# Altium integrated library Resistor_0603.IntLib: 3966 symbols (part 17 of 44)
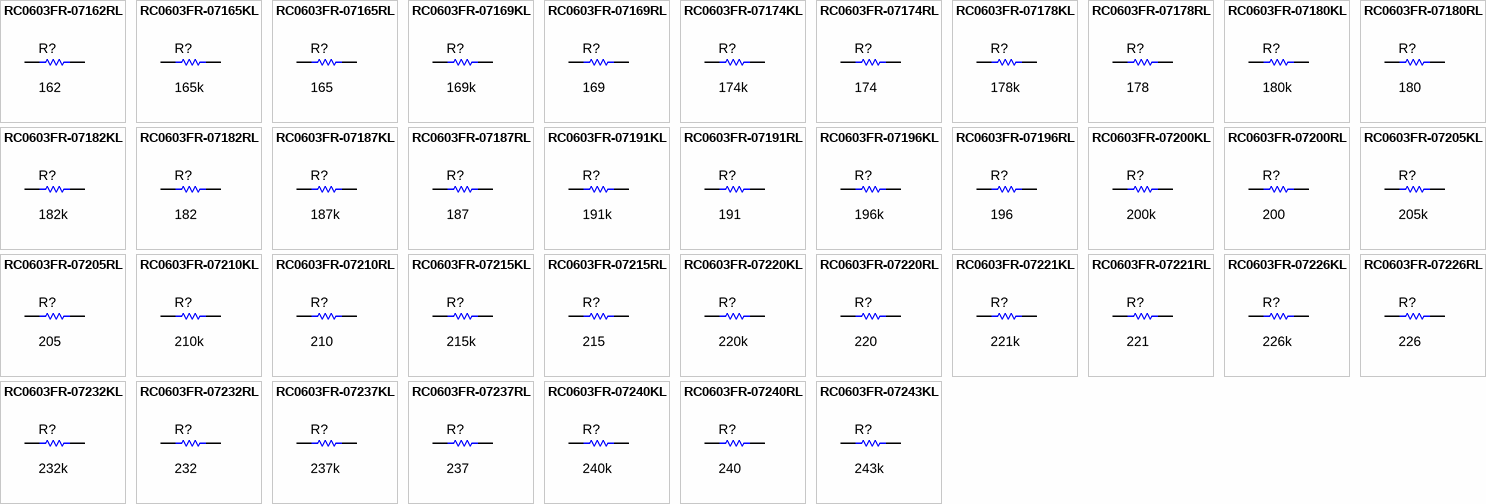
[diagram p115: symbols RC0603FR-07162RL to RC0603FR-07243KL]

## RC0603FR-07240RL
designator R?  ValueDisplayed: 240  (hidden comment: RC0603FR-07240RL)
RES, 240, 1%, 0.1 W, 0603; Manufacturer: Yageo America; CompType: Resistor; Value: 240; Value_Code: 240R; Tolerance_%: 1; Power_W: 0.1; Value2: 0.1W; VDC_V: 150; TempCo: 200 ppm/C; SizeArea_mm2: 1.28; SizeX_mm: 1.6; SizeY_mm: 0.8; U/M: EA; AEC Category: Q200; Green_Lifecycle: Active; Green_REACh: Passed
signal-integrity model Resistor
simulation model Resistor
footprint 0603
footprint 0603M
footprint 0603L
footprint 0603_HV
footprint 0603S
pins: 1, 2

## RC0603FR-07243KL
designator R?  ValueDisplayed: 243k  (hidden comment: RC0603FR-07243KL)
RES, 243 k, 1%, 0.1 W, 0603; Manufacturer: Yageo America; CompType: Resistor; Value: 243k; Res_ohm: 243000; Tolerance_%: 1; Power_W: 0.1; Value2: 0.1W; VDC_V: 150; TempCo: 200 ppm/C; SizeArea_mm2: 1.28; SizeX_mm: 1.6; SizeY_mm: 0.8; EIA_Code: E96; U/M: EA; AEC Category: Q200; Green_Lifecycle: Active; Green_REACh: Passed
signal-integrity model Resistor
simulation model Resistor
footprint 0603
footprint 0603M
footprint 0603L
footprint 0603_HV
footprint 0603S
pins: 1, 2

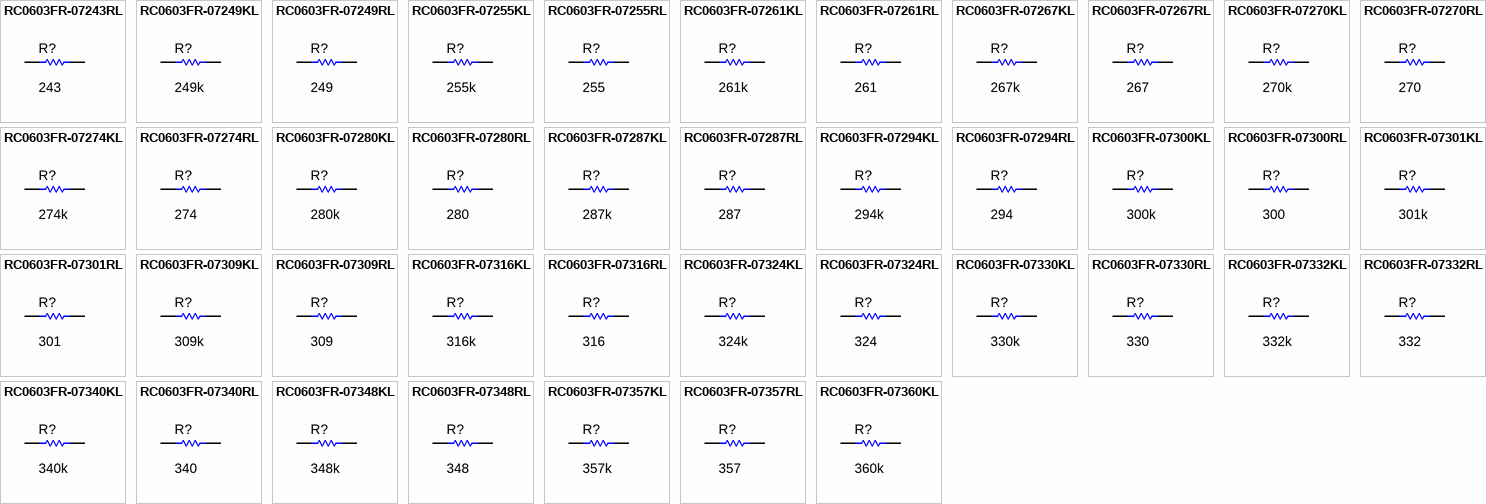
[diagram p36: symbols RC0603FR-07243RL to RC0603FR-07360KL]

## RC0603FR-07243RL
designator R?  ValueDisplayed: 243  (hidden comment: RC0603FR-07243RL)
RES, 243, 1%, 0.1 W, 0603; Manufacturer: Yageo America; CompType: Resistor; Value: 243; Value_Code: 243R; Tolerance_%: 1; Power_W: 0.1; Value2: 0.1W; VDC_V: 150; TempCo: 200 ppm/C; SizeArea_mm2: 1.28; SizeX_mm: 1.6; SizeY_mm: 0.8; EIA_Code: E96; U/M: EA; AEC Category: Q200
signal-integrity model Resistor
simulation model Resistor
footprint 0603
footprint 0603M
footprint 0603L
footprint 0603_HV
footprint 0603S
pins: 1, 2

## RC0603FR-07249KL
designator R?  ValueDisplayed: 249k  (hidden comment: RC0603FR-07249KL)
RES, 249 k, 1%, 0.1 W, 0603; Manufacturer: Yageo America; CompType: Resistor; Value: 249k; Res_ohm: 249000; Tolerance_%: 1; Power_W: 0.1; Value2: 0.1W; VDC_V: 150; TempCo: 200 ppm/C; SizeArea_mm2: 1.28; SizeX_mm: 1.6; SizeY_mm: 0.8; EIA_Code: E96; U/M: EA; AEC Category: Q200; Green_Lifecycle: Active; Green_REACh: Passed
signal-integrity model Resistor
simulation model Resistor
footprint 0603
footprint 0603M
footprint 0603L
footprint 0603_HV
footprint 0603S
pins: 1, 2

## RC0603FR-07249RL
designator R?  ValueDisplayed: 249  (hidden comment: RC0603FR-07249RL)
RES, 249, 1%, 0.1 W, 0603; Manufacturer: Yageo America; CompType: Resistor; Value: 249; Value_Code: 249R; Tolerance_%: 1; Power_W: 0.1; Value2: 0.1W; VDC_V: 150; TempCo: 200 ppm/C; SizeArea_mm2: 1.28; SizeX_mm: 1.6; SizeY_mm: 0.8; EIA_Code: E96; U/M: EA; AEC Category: Q200; Green_Lifecycle: Active; Green_REACh: Passed
signal-integrity model Resistor
simulation model Resistor
footprint 0603
footprint 0603M
footprint 0603L
footprint 0603_HV
footprint 0603S
pins: 1, 2

## RC0603FR-07255KL
designator R?  ValueDisplayed: 255k  (hidden comment: RC0603FR-07255KL)
RES, 255 k, 1%, 0.1 W, 0603; Manufacturer: Yageo America; CompType: Resistor; Value: 255k; Res_ohm: 255000; Tolerance_%: 1; Power_W: 0.1; Value2: 0.1W; VDC_V: 150; TempCo: 200 ppm/C; SizeArea_mm2: 1.28; SizeX_mm: 1.6; SizeY_mm: 0.8; EIA_Code: E96; U/M: EA; AEC Category: Q200; Green_Lifecycle: Active; Green_REACh: Passed
signal-integrity model Resistor
simulation model Resistor
footprint 0603
footprint 0603M
footprint 0603L
footprint 0603_HV
footprint 0603S
pins: 1, 2

## RC0603FR-07255RL
designator R?  ValueDisplayed: 255  (hidden comment: RC0603FR-07255RL)
RES, 255, 1%, 0.1 W, 0603; Manufacturer: Yageo America; CompType: Resistor; Value: 255; Value_Code: 255R; Tolerance_%: 1; Power_W: 0.1; Value2: 0.1W; VDC_V: 150; TempCo: 200 ppm/C; SizeArea_mm2: 1.28; SizeX_mm: 1.6; SizeY_mm: 0.8; EIA_Code: E96; U/M: EA; AEC Category: Q200
signal-integrity model Resistor
simulation model Resistor
footprint 0603
footprint 0603M
footprint 0603L
footprint 0603_HV
footprint 0603S
pins: 1, 2

## RC0603FR-07261KL
designator R?  ValueDisplayed: 261k  (hidden comment: RC0603FR-07261KL)
RES, 261 k, 1%, 0.1 W, 0603; Manufacturer: Yageo America; CompType: Resistor; Value: 261k; Res_ohm: 261000; Tolerance_%: 1; Power_W: 0.1; Value2: 0.1W; VDC_V: 150; TempCo: 200 ppm/C; SizeArea_mm2: 1.28; SizeX_mm: 1.6; SizeY_mm: 0.8; EIA_Code: E96; U/M: EA; AEC Category: Q200
signal-integrity model Resistor
simulation model Resistor
footprint 0603
footprint 0603M
footprint 0603L
footprint 0603_HV
footprint 0603S
pins: 1, 2

## RC0603FR-07261RL
designator R?  ValueDisplayed: 261  (hidden comment: RC0603FR-07261RL)
RES, 261, 1%, 0.1 W, 0603; Manufacturer: Yageo America; CompType: Resistor; Value: 261; Value_Code: 261R; Tolerance_%: 1; Power_W: 0.1; Value2: 0.1W; VDC_V: 150; TempCo: 200 ppm/C; SizeArea_mm2: 1.28; SizeX_mm: 1.6; SizeY_mm: 0.8; EIA_Code: E96; U/M: EA; AEC Category: Q200
signal-integrity model Resistor
simulation model Resistor
footprint 0603
footprint 0603M
footprint 0603L
footprint 0603_HV
footprint 0603S
pins: 1, 2

## RC0603FR-07267KL
designator R?  ValueDisplayed: 267k  (hidden comment: RC0603FR-07267KL)
RES, 267 k, 1%, 0.1 W, 0603; Manufacturer: Yageo America; CompType: Resistor; Value: 267k; Res_ohm: 267000; Tolerance_%: 1; Power_W: 0.1; Value2: 0.1W; VDC_V: 150; TempCo: 200 ppm/C; SizeArea_mm2: 1.28; SizeX_mm: 1.6; SizeY_mm: 0.8; EIA_Code: E96; U/M: EA; AEC Category: Q200
signal-integrity model Resistor
simulation model Resistor
footprint 0603
footprint 0603M
footprint 0603L
footprint 0603_HV
footprint 0603S
pins: 1, 2

## RC0603FR-07267RL
designator R?  ValueDisplayed: 267  (hidden comment: RC0603FR-07267RL)
RES, 267, 1%, 0.1 W, 0603; Manufacturer: Yageo America; CompType: Resistor; Value: 267; Value_Code: 267R; Tolerance_%: 1; Power_W: 0.1; Value2: 0.1W; VDC_V: 150; TempCo: 200 ppm/C; SizeArea_mm2: 1.28; SizeX_mm: 1.6; SizeY_mm: 0.8; EIA_Code: E96; U/M: EA; AEC Category: Q200
signal-integrity model Resistor
simulation model Resistor
footprint 0603
footprint 0603M
footprint 0603L
footprint 0603_HV
footprint 0603S
pins: 1, 2

## RC0603FR-07270KL
designator R?  ValueDisplayed: 270k  (hidden comment: RC0603FR-07270KL)
RES, 270 k, 1%, 0.1 W, 0603; Manufacturer: Yageo America; CompType: Resistor; Value: 270k; Res_ohm: 270000; Tolerance_%: 1; Power_W: 0.1; Value2: 0.1W; VDC_V: 150; TempCo: 200 ppm/C; SizeArea_mm2: 1.28; SizeX_mm: 1.6; SizeY_mm: 0.8; U/M: EA; AEC Category: Q200; Green_Lifecycle: Active; Green_REACh: Passed
signal-integrity model Resistor
simulation model Resistor
footprint 0603
footprint 0603M
footprint 0603L
footprint 0603_HV
footprint 0603S
pins: 1, 2

## RC0603FR-07270RL
designator R?  ValueDisplayed: 270  (hidden comment: RC0603FR-07270RL)
RES, 270, 1%, 0.1 W, 0603; Manufacturer: Yageo America; CompType: Resistor; Value: 270; Value_Code: 270R; Tolerance_%: 1; Power_W: 0.1; Value2: 0.1W; VDC_V: 150; TempCo: 200 ppm/C; SizeArea_mm2: 1.28; SizeX_mm: 1.6; SizeY_mm: 0.8; U/M: EA; AEC Category: Q200; Green_Lifecycle: Active; Green_REACh: Passed
signal-integrity model Resistor
simulation model Resistor
footprint 0603
footprint 0603M
footprint 0603L
footprint 0603_HV
footprint 0603S
pins: 1, 2

## RC0603FR-07274KL
designator R?  ValueDisplayed: 274k  (hidden comment: RC0603FR-07274KL)
RES, 274 k, 1%, 0.1 W, 0603; Manufacturer: Yageo America; CompType: Resistor; Value: 274k; Res_ohm: 274000; Tolerance_%: 1; Power_W: 0.1; Value2: 0.1W; VDC_V: 150; TempCo: 200 ppm/C; SizeArea_mm2: 1.28; SizeX_mm: 1.6; SizeY_mm: 0.8; EIA_Code: E96; U/M: EA; AEC Category: Q200; Green_Lifecycle: Active; Green_REACh: Passed
signal-integrity model Resistor
simulation model Resistor
footprint 0603
footprint 0603M
footprint 0603L
footprint 0603_HV
footprint 0603S
pins: 1, 2

## RC0603FR-07274RL
designator R?  ValueDisplayed: 274  (hidden comment: RC0603FR-07274RL)
RES, 274, 1%, 0.1 W, 0603; Manufacturer: Yageo America; CompType: Resistor; Value: 274; Value_Code: 274R; Tolerance_%: 1; Power_W: 0.1; Value2: 0.1W; VDC_V: 150; TempCo: 200 ppm/C; SizeArea_mm2: 1.28; SizeX_mm: 1.6; SizeY_mm: 0.8; EIA_Code: E96; U/M: EA; AEC Category: Q200
signal-integrity model Resistor
simulation model Resistor
footprint 0603
footprint 0603M
footprint 0603L
footprint 0603_HV
footprint 0603S
pins: 1, 2

## RC0603FR-07280KL
designator R?  ValueDisplayed: 280k  (hidden comment: RC0603FR-07280KL)
RES, 280 k, 1%, 0.1 W, 0603; Manufacturer: Yageo America; CompType: Resistor; Value: 280k; Res_ohm: 280000; Tolerance_%: 1; Power_W: 0.1; Value2: 0.1W; VDC_V: 150; TempCo: 200 ppm/C; SizeArea_mm2: 1.28; SizeX_mm: 1.6; SizeY_mm: 0.8; EIA_Code: E96; U/M: EA; AEC Category: Q200; Green_Lifecycle: Active; Green_REACh: Passed
signal-integrity model Resistor
simulation model Resistor
footprint 0603
footprint 0603M
footprint 0603L
footprint 0603_HV
footprint 0603S
pins: 1, 2

## RC0603FR-07280RL
designator R?  ValueDisplayed: 280  (hidden comment: RC0603FR-07280RL)
RES, 280, 1%, 0.1 W, 0603; Manufacturer: Yageo America; CompType: Resistor; Value: 280; Value_Code: 280R; Tolerance_%: 1; Power_W: 0.1; Value2: 0.1W; VDC_V: 150; TempCo: 200 ppm/C; SizeArea_mm2: 1.28; SizeX_mm: 1.6; SizeY_mm: 0.8; EIA_Code: E96; U/M: EA; AEC Category: Q200
signal-integrity model Resistor
simulation model Resistor
footprint 0603
footprint 0603M
footprint 0603L
footprint 0603_HV
footprint 0603S
pins: 1, 2

## RC0603FR-07287KL
designator R?  ValueDisplayed: 287k  (hidden comment: RC0603FR-07287KL)
RES, 287 k, 1%, 0.1 W, 0603; Manufacturer: Yageo America; CompType: Resistor; Value: 287k; Res_ohm: 287000; Tolerance_%: 1; Power_W: 0.1; Value2: 0.1W; VDC_V: 150; TempCo: 200 ppm/C; SizeArea_mm2: 1.28; SizeX_mm: 1.6; SizeY_mm: 0.8; EIA_Code: E96; U/M: EA; AEC Category: Q200
signal-integrity model Resistor
simulation model Resistor
footprint 0603
footprint 0603M
footprint 0603L
footprint 0603_HV
footprint 0603S
pins: 1, 2

## RC0603FR-07287RL
designator R?  ValueDisplayed: 287  (hidden comment: RC0603FR-07287RL)
RES, 287, 1%, 0.1 W, 0603; Manufacturer: Yageo America; CompType: Resistor; Value: 287; Value_Code: 287R; Tolerance_%: 1; Power_W: 0.1; Value2: 0.1W; VDC_V: 150; TempCo: 200 ppm/C; SizeArea_mm2: 1.28; SizeX_mm: 1.6; SizeY_mm: 0.8; EIA_Code: E96; U/M: EA; AEC Category: Q200
signal-integrity model Resistor
simulation model Resistor
footprint 0603
footprint 0603M
footprint 0603L
footprint 0603_HV
footprint 0603S
pins: 1, 2

## RC0603FR-07294KL
designator R?  ValueDisplayed: 294k  (hidden comment: RC0603FR-07294KL)
RES, 294 k, 1%, 0.1 W, 0603; Manufacturer: Yageo America; CompType: Resistor; Value: 294k; Res_ohm: 294000; Tolerance_%: 1; Power_W: 0.1; Value2: 0.1W; VDC_V: 150; TempCo: 200 ppm/C; SizeArea_mm2: 1.28; SizeX_mm: 1.6; SizeY_mm: 0.8; EIA_Code: E96; U/M: EA; AEC Category: Q200; Green_Lifecycle: Active; Green_REACh: Passed
signal-integrity model Resistor
simulation model Resistor
footprint 0603
footprint 0603M
footprint 0603L
footprint 0603_HV
footprint 0603S
pins: 1, 2

## RC0603FR-07294RL
designator R?  ValueDisplayed: 294  (hidden comment: RC0603FR-07294RL)
RES, 294, 1%, 0.1 W, 0603; Manufacturer: Yageo America; CompType: Resistor; Value: 294; Value_Code: 294R; Tolerance_%: 1; Power_W: 0.1; Value2: 0.1W; VDC_V: 150; TempCo: 200 ppm/C; SizeArea_mm2: 1.28; SizeX_mm: 1.6; SizeY_mm: 0.8; EIA_Code: E96; U/M: EA; AEC Category: Q200
signal-integrity model Resistor
simulation model Resistor
footprint 0603
footprint 0603M
footprint 0603L
footprint 0603_HV
footprint 0603S
pins: 1, 2

## RC0603FR-07300KL
designator R?  ValueDisplayed: 300k  (hidden comment: RC0603FR-07300KL)
RES, 300 k, 1%, 0.1 W, 0603; Manufacturer: Yageo America; CompType: Resistor; Value: 300k; Res_ohm: 300000; Tolerance_%: 1; Power_W: 0.1; Value2: 0.1W; VDC_V: 150; TempCo: 200 ppm/C; SizeArea_mm2: 1.28; SizeX_mm: 1.6; SizeY_mm: 0.8; U/M: EA; AEC Category: Q200; Green_Lifecycle: Active; Green_REACh: Passed
signal-integrity model Resistor
simulation model Resistor
footprint 0603
footprint 0603M
footprint 0603L
footprint 0603_HV
footprint 0603S
pins: 1, 2

## RC0603FR-07300RL
designator R?  ValueDisplayed: 300  (hidden comment: RC0603FR-07300RL)
RES, 300, 1%, 0.1 W, 0603; Manufacturer: Yageo America; CompType: Resistor; Value: 300; Value_Code: 300R; Tolerance_%: 1; Power_W: 0.1; Value2: 0.1W; VDC_V: 150; TempCo: 200 ppm/C; SizeArea_mm2: 1.28; SizeX_mm: 1.6; SizeY_mm: 0.8; U/M: EA; AEC Category: Q200; Green_Lifecycle: Active; Green_REACh: Passed
signal-integrity model Resistor
simulation model Resistor
footprint 0603
footprint 0603M
footprint 0603L
footprint 0603_HV
footprint 0603S
pins: 1, 2

## RC0603FR-07301KL
designator R?  ValueDisplayed: 301k  (hidden comment: RC0603FR-07301KL)
RES, 301 k, 1%, 0.1 W, 0603; Manufacturer: Yageo America; CompType: Resistor; Value: 301k; Res_ohm: 301000; Tolerance_%: 1; Power_W: 0.1; Value2: 0.1W; VDC_V: 150; TempCo: 200 ppm/C; SizeArea_mm2: 1.28; SizeX_mm: 1.6; SizeY_mm: 0.8; EIA_Code: E96; U/M: EA; AEC Category: Q200; Green_Lifecycle: Active; Green_REACh: Passed
signal-integrity model Resistor
simulation model Resistor
footprint 0603
footprint 0603M
footprint 0603L
footprint 0603_HV
footprint 0603S
pins: 1, 2

## RC0603FR-07301RL
designator R?  ValueDisplayed: 301  (hidden comment: RC0603FR-07301RL)
RES, 301, 1%, 0.1 W, 0603; Manufacturer: Yageo America; CompType: Resistor; Value: 301; Value_Code: 301R; Tolerance_%: 1; Power_W: 0.1; Value2: 0.1W; VDC_V: 150; TempCo: 200 ppm/C; SizeArea_mm2: 1.28; SizeX_mm: 1.6; SizeY_mm: 0.8; EIA_Code: E96; U/M: EA; AEC Category: Q200; Green_Lifecycle: Active; Green_REACh: Passed
signal-integrity model Resistor
simulation model Resistor
footprint 0603
footprint 0603M
footprint 0603L
footprint 0603_HV
footprint 0603S
pins: 1, 2

## RC0603FR-07309KL
designator R?  ValueDisplayed: 309k  (hidden comment: RC0603FR-07309KL)
RES, 309 k, 1%, 0.1 W, 0603; Manufacturer: Yageo America; CompType: Resistor; Value: 309k; Res_ohm: 309000; Tolerance_%: 1; Power_W: 0.1; Value2: 0.1W; VDC_V: 150; TempCo: 200 ppm/C; SizeArea_mm2: 1.28; SizeX_mm: 1.6; SizeY_mm: 0.8; EIA_Code: E96; U/M: EA; AEC Category: Q200; Green_Lifecycle: Active; Green_REACh: Passed
signal-integrity model Resistor
simulation model Resistor
footprint 0603
footprint 0603M
footprint 0603L
footprint 0603_HV
footprint 0603S
pins: 1, 2

## RC0603FR-07309RL
designator R?  ValueDisplayed: 309  (hidden comment: RC0603FR-07309RL)
RES, 309, 1%, 0.1 W, 0603; Manufacturer: Yageo America; CompType: Resistor; Value: 309; Value_Code: 309R; Tolerance_%: 1; Power_W: 0.1; Value2: 0.1W; VDC_V: 150; TempCo: 200 ppm/C; SizeArea_mm2: 1.28; SizeX_mm: 1.6; SizeY_mm: 0.8; EIA_Code: E96; U/M: EA; AEC Category: Q200
signal-integrity model Resistor
simulation model Resistor
footprint 0603
footprint 0603M
footprint 0603L
footprint 0603_HV
footprint 0603S
pins: 1, 2

## RC0603FR-07316KL
designator R?  ValueDisplayed: 316k  (hidden comment: RC0603FR-07316KL)
RES, 316 k, 1%, 0.1 W, 0603; Manufacturer: Yageo America; CompType: Resistor; Value: 316k; Res_ohm: 316000; Tolerance_%: 1; Power_W: 0.1; Value2: 0.1W; VDC_V: 150; TempCo: 200 ppm/C; SizeArea_mm2: 1.28; SizeX_mm: 1.6; SizeY_mm: 0.8; EIA_Code: E96; U/M: EA; AEC Category: Q200; Green_Lifecycle: Active; Green_REACh: Passed
signal-integrity model Resistor
simulation model Resistor
footprint 0603
footprint 0603M
footprint 0603L
footprint 0603_HV
footprint 0603S
pins: 1, 2

## RC0603FR-07316RL
designator R?  ValueDisplayed: 316  (hidden comment: RC0603FR-07316RL)
RES, 316, 1%, 0.1 W, 0603; Manufacturer: Yageo America; CompType: Resistor; Value: 316; Value_Code: 316R; Tolerance_%: 1; Power_W: 0.1; Value2: 0.1W; VDC_V: 150; TempCo: 200 ppm/C; SizeArea_mm2: 1.28; SizeX_mm: 1.6; SizeY_mm: 0.8; EIA_Code: E96; U/M: EA; AEC Category: Q200
signal-integrity model Resistor
simulation model Resistor
footprint 0603
footprint 0603M
footprint 0603L
footprint 0603_HV
footprint 0603S
pins: 1, 2

## RC0603FR-07324KL
designator R?  ValueDisplayed: 324k  (hidden comment: RC0603FR-07324KL)
RES, 324 k, 1%, 0.1 W, 0603; Manufacturer: Yageo America; CompType: Resistor; Value: 324k; Res_ohm: 324000; Tolerance_%: 1; Power_W: 0.1; Value2: 0.1W; VDC_V: 150; TempCo: 200 ppm/C; SizeArea_mm2: 1.28; SizeX_mm: 1.6; SizeY_mm: 0.8; EIA_Code: E96; U/M: EA; AEC Category: Q200; Green_Lifecycle: Active; Green_REACh: Passed
signal-integrity model Resistor
simulation model Resistor
footprint 0603
footprint 0603M
footprint 0603L
footprint 0603_HV
footprint 0603S
pins: 1, 2

## RC0603FR-07324RL
designator R?  ValueDisplayed: 324  (hidden comment: RC0603FR-07324RL)
RES, 324, 1%, 0.1 W, 0603; Manufacturer: Yageo America; CompType: Resistor; Value: 324; Value_Code: 324R; Tolerance_%: 1; Power_W: 0.1; Value2: 0.1W; VDC_V: 150; TempCo: 200 ppm/C; SizeArea_mm2: 1.28; SizeX_mm: 1.6; SizeY_mm: 0.8; EIA_Code: E96; U/M: EA; AEC Category: Q200; Green_Lifecycle: Active; Green_REACh: Passed
signal-integrity model Resistor
simulation model Resistor
footprint 0603
footprint 0603M
footprint 0603L
footprint 0603_HV
footprint 0603S
pins: 1, 2

## RC0603FR-07330KL
designator R?  ValueDisplayed: 330k  (hidden comment: RC0603FR-07330KL)
RES, 330 k, 1%, 0.1 W, 0603; Manufacturer: Yageo America; CompType: Resistor; Value: 330k; Res_ohm: 330000; Tolerance_%: 1; Power_W: 0.1; Value2: 0.1W; VDC_V: 150; TempCo: 200 ppm/C; SizeArea_mm2: 1.28; SizeX_mm: 1.6; SizeY_mm: 0.8; U/M: EA; AEC Category: Q200; Green_Lifecycle: Active; Green_REACh: Passed
signal-integrity model Resistor
simulation model Resistor
footprint 0603
footprint 0603M
footprint 0603L
footprint 0603_HV
footprint 0603S
pins: 1, 2

## RC0603FR-07330RL
designator R?  ValueDisplayed: 330  (hidden comment: RC0603FR-07330RL)
RES, 330, 1%, 0.1 W, 0603; Manufacturer: Yageo America; CompType: Resistor; Value: 330; Value_Code: 330R; Tolerance_%: 1; Power_W: 0.1; Value2: 0.1W; VDC_V: 150; TempCo: 200 ppm/C; SizeArea_mm2: 1.28; SizeX_mm: 1.6; SizeY_mm: 0.8; U/M: EA; AEC Category: Q200; Green_Lifecycle: Active; Green_REACh: Passed
signal-integrity model Resistor
simulation model Resistor
footprint 0603
footprint 0603M
footprint 0603L
footprint 0603_HV
footprint 0603S
pins: 1, 2

## RC0603FR-07332KL
designator R?  ValueDisplayed: 332k  (hidden comment: RC0603FR-07332KL)
RES, 332 k, 1%, 0.1 W, 0603; Manufacturer: Yageo America; CompType: Resistor; Value: 332k; Res_ohm: 332000; Tolerance_%: 1; Power_W: 0.1; Value2: 0.1W; VDC_V: 150; TempCo: 200 ppm/C; SizeArea_mm2: 1.28; SizeX_mm: 1.6; SizeY_mm: 0.8; EIA_Code: E96; U/M: EA; AEC Category: Q200; Green_Lifecycle: Active; Green_REACh: Passed
signal-integrity model Resistor
simulation model Resistor
footprint 0603
footprint 0603M
footprint 0603L
footprint 0603_HV
footprint 0603S
pins: 1, 2

## RC0603FR-07332RL
designator R?  ValueDisplayed: 332  (hidden comment: RC0603FR-07332RL)
RES, 332, 1%, 0.1 W, 0603; Manufacturer: Yageo America; CompType: Resistor; Value: 332; Value_Code: 332R; Tolerance_%: 1; Power_W: 0.1; Value2: 0.1W; VDC_V: 150; TempCo: 200 ppm/C; SizeArea_mm2: 1.28; SizeX_mm: 1.6; SizeY_mm: 0.8; EIA_Code: E96; U/M: EA; AEC Category: Q200; Green_Lifecycle: Active; Green_REACh: Passed
signal-integrity model Resistor
simulation model Resistor
footprint 0603
footprint 0603M
footprint 0603L
footprint 0603_HV
footprint 0603S
pins: 1, 2

## RC0603FR-07340KL
designator R?  ValueDisplayed: 340k  (hidden comment: RC0603FR-07340KL)
RES, 340 k, 1%, 0.1 W, 0603; Manufacturer: Yageo America; CompType: Resistor; Value: 340k; Res_ohm: 340000; Tolerance_%: 1; Power_W: 0.1; Value2: 0.1W; VDC_V: 150; TempCo: 200 ppm/C; SizeArea_mm2: 1.28; SizeX_mm: 1.6; SizeY_mm: 0.8; EIA_Code: E96; U/M: EA; AEC Category: Q200; Green_Lifecycle: Active; Green_REACh: Passed
signal-integrity model Resistor
simulation model Resistor
footprint 0603
footprint 0603M
footprint 0603L
footprint 0603_HV
footprint 0603S
pins: 1, 2

## RC0603FR-07340RL
designator R?  ValueDisplayed: 340  (hidden comment: RC0603FR-07340RL)
RES, 340, 1%, 0.1 W, 0603; Manufacturer: Yageo America; CompType: Resistor; Value: 340; Value_Code: 340R; Tolerance_%: 1; Power_W: 0.1; Value2: 0.1W; VDC_V: 150; TempCo: 200 ppm/C; SizeArea_mm2: 1.28; SizeX_mm: 1.6; SizeY_mm: 0.8; EIA_Code: E96; U/M: EA; AEC Category: Q200
signal-integrity model Resistor
simulation model Resistor
footprint 0603
footprint 0603M
footprint 0603L
footprint 0603_HV
footprint 0603S
pins: 1, 2

## RC0603FR-07348KL
designator R?  ValueDisplayed: 348k  (hidden comment: RC0603FR-07348KL)
RES, 348 k, 1%, 0.1 W, 0603; Manufacturer: Yageo America; CompType: Resistor; Value: 348k; Res_ohm: 348000; Tolerance_%: 1; Power_W: 0.1; Value2: 0.1W; VDC_V: 150; TempCo: 200 ppm/C; SizeArea_mm2: 1.28; SizeX_mm: 1.6; SizeY_mm: 0.8; EIA_Code: E96; U/M: EA; AEC Category: Q200
signal-integrity model Resistor
simulation model Resistor
footprint 0603
footprint 0603M
footprint 0603L
footprint 0603_HV
footprint 0603S
pins: 1, 2

## RC0603FR-07348RL
designator R?  ValueDisplayed: 348  (hidden comment: RC0603FR-07348RL)
RES, 348, 1%, 0.1 W, 0603; Manufacturer: Yageo America; CompType: Resistor; Value: 348; Value_Code: 348R; Tolerance_%: 1; Power_W: 0.1; Value2: 0.1W; VDC_V: 150; TempCo: 200 ppm/C; SizeArea_mm2: 1.28; SizeX_mm: 1.6; SizeY_mm: 0.8; EIA_Code: E96; U/M: EA; AEC Category: Q200; Green_Lifecycle: Active; Green_REACh: Passed
signal-integrity model Resistor
simulation model Resistor
footprint 0603
footprint 0603M
footprint 0603L
footprint 0603_HV
footprint 0603S
pins: 1, 2

## RC0603FR-07357KL
designator R?  ValueDisplayed: 357k  (hidden comment: RC0603FR-07357KL)
RES, 357 k, 1%, 0.1 W, 0603; Manufacturer: Yageo America; CompType: Resistor; Value: 357k; Res_ohm: 357000; Tolerance_%: 1; Power_W: 0.1; Value2: 0.1W; VDC_V: 150; TempCo: 200 ppm/C; SizeArea_mm2: 1.28; SizeX_mm: 1.6; SizeY_mm: 0.8; EIA_Code: E96; U/M: EA; AEC Category: Q200
signal-integrity model Resistor
simulation model Resistor
footprint 0603
footprint 0603M
footprint 0603L
footprint 0603_HV
footprint 0603S
pins: 1, 2

## RC0603FR-07357RL
designator R?  ValueDisplayed: 357  (hidden comment: RC0603FR-07357RL)
RES, 357, 1%, 0.1 W, 0603; Manufacturer: Yageo America; CompType: Resistor; Value: 357; Value_Code: 357R; Tolerance_%: 1; Power_W: 0.1; Value2: 0.1W; VDC_V: 150; TempCo: 200 ppm/C; SizeArea_mm2: 1.28; SizeX_mm: 1.6; SizeY_mm: 0.8; EIA_Code: E96; U/M: EA; AEC Category: Q200; Green_Lifecycle: Active; Green_REACh: Passed
signal-integrity model Resistor
simulation model Resistor
footprint 0603
footprint 0603M
footprint 0603L
footprint 0603_HV
footprint 0603S
pins: 1, 2

## RC0603FR-07360KL
designator R?  ValueDisplayed: 360k  (hidden comment: RC0603FR-07360KL)
RES, 360 k, 1%, 0.1 W, 0603; Manufacturer: Yageo America; CompType: Resistor; Value: 360k; Res_ohm: 360000; Tolerance_%: 1; Power_W: 0.1; Value2: 0.1W; VDC_V: 150; TempCo: 200 ppm/C; SizeArea_mm2: 1.28; SizeX_mm: 1.6; SizeY_mm: 0.8; U/M: EA; AEC Category: Q200
signal-integrity model Resistor
simulation model Resistor
footprint 0603
footprint 0603M
footprint 0603L
footprint 0603_HV
footprint 0603S
pins: 1, 2

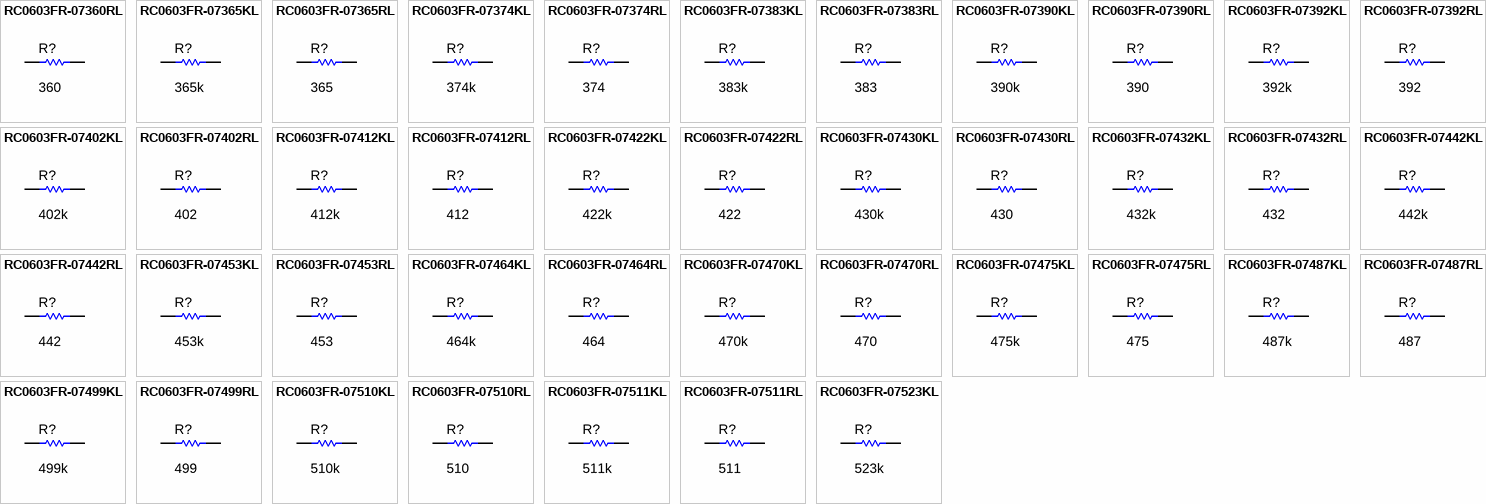
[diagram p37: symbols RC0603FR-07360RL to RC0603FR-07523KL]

## RC0603FR-07360RL
designator R?  ValueDisplayed: 360  (hidden comment: RC0603FR-07360RL)
RES, 360, 1%, 0.1 W, 0603; Manufacturer: Yageo America; CompType: Resistor; Value: 360; Value_Code: 360R; Tolerance_%: 1; Power_W: 0.1; Value2: 0.1W; VDC_V: 150; TempCo: 200 ppm/C; SizeArea_mm2: 1.28; SizeX_mm: 1.6; SizeY_mm: 0.8; U/M: EA; AEC Category: Q200; Green_Lifecycle: Active; Green_REACh: Passed
signal-integrity model Resistor
simulation model Resistor
footprint 0603
footprint 0603M
footprint 0603L
footprint 0603_HV
footprint 0603S
pins: 1, 2

## RC0603FR-07365KL
designator R?  ValueDisplayed: 365k  (hidden comment: RC0603FR-07365KL)
RES, 365 k, 1%, 0.1 W, 0603; Manufacturer: Yageo America; CompType: Resistor; Value: 365k; Res_ohm: 365000; Tolerance_%: 1; Power_W: 0.1; Value2: 0.1W; VDC_V: 150; TempCo: 200 ppm/C; SizeArea_mm2: 1.28; SizeX_mm: 1.6; SizeY_mm: 0.8; EIA_Code: E96; U/M: EA; AEC Category: Q200; Green_Lifecycle: Active; Green_REACh: Passed
signal-integrity model Resistor
simulation model Resistor
footprint 0603
footprint 0603M
footprint 0603L
footprint 0603_HV
footprint 0603S
pins: 1, 2

## RC0603FR-07365RL
designator R?  ValueDisplayed: 365  (hidden comment: RC0603FR-07365RL)
RES, 365, 1%, 0.1 W, 0603; Manufacturer: Yageo America; CompType: Resistor; Value: 365; Value_Code: 365R; Tolerance_%: 1; Power_W: 0.1; Value2: 0.1W; VDC_V: 150; TempCo: 200 ppm/C; SizeArea_mm2: 1.28; SizeX_mm: 1.6; SizeY_mm: 0.8; EIA_Code: E96; U/M: EA; AEC Category: Q200
signal-integrity model Resistor
simulation model Resistor
footprint 0603
footprint 0603M
footprint 0603L
footprint 0603_HV
footprint 0603S
pins: 1, 2

## RC0603FR-07374KL
designator R?  ValueDisplayed: 374k  (hidden comment: RC0603FR-07374KL)
RES, 374 k, 1%, 0.1 W, 0603; Manufacturer: Yageo America; CompType: Resistor; Value: 374k; Res_ohm: 374000; Tolerance_%: 1; Power_W: 0.1; Value2: 0.1W; VDC_V: 150; TempCo: 200 ppm/C; SizeArea_mm2: 1.28; SizeX_mm: 1.6; SizeY_mm: 0.8; EIA_Code: E96; U/M: EA; AEC Category: Q200
signal-integrity model Resistor
simulation model Resistor
footprint 0603
footprint 0603M
footprint 0603L
footprint 0603_HV
footprint 0603S
pins: 1, 2

## RC0603FR-07374RL
designator R?  ValueDisplayed: 374  (hidden comment: RC0603FR-07374RL)
RES, 374, 1%, 0.1 W, 0603; Manufacturer: Yageo America; CompType: Resistor; Value: 374; Value_Code: 374R; Tolerance_%: 1; Power_W: 0.1; Value2: 0.1W; VDC_V: 150; TempCo: 200 ppm/C; SizeArea_mm2: 1.28; SizeX_mm: 1.6; SizeY_mm: 0.8; EIA_Code: E96; U/M: EA; AEC Category: Q200
signal-integrity model Resistor
simulation model Resistor
footprint 0603
footprint 0603M
footprint 0603L
footprint 0603_HV
footprint 0603S
pins: 1, 2

## RC0603FR-07383KL
designator R?  ValueDisplayed: 383k  (hidden comment: RC0603FR-07383KL)
RES, 383 k, 1%, 0.1 W, 0603; Manufacturer: Yageo America; CompType: Resistor; Value: 383k; Res_ohm: 383000; Tolerance_%: 1; Power_W: 0.1; Value2: 0.1W; VDC_V: 150; TempCo: 200 ppm/C; SizeArea_mm2: 1.28; SizeX_mm: 1.6; SizeY_mm: 0.8; EIA_Code: E96; U/M: EA; AEC Category: Q200
signal-integrity model Resistor
simulation model Resistor
footprint 0603
footprint 0603M
footprint 0603L
footprint 0603_HV
footprint 0603S
pins: 1, 2

## RC0603FR-07383RL
designator R?  ValueDisplayed: 383  (hidden comment: RC0603FR-07383RL)
RES, 383, 1%, 0.1 W, 0603; Manufacturer: Yageo America; CompType: Resistor; Value: 383; Value_Code: 383R; Tolerance_%: 1; Power_W: 0.1; Value2: 0.1W; VDC_V: 150; TempCo: 200 ppm/C; SizeArea_mm2: 1.28; SizeX_mm: 1.6; SizeY_mm: 0.8; EIA_Code: E96; U/M: EA; AEC Category: Q200
signal-integrity model Resistor
simulation model Resistor
footprint 0603
footprint 0603M
footprint 0603L
footprint 0603_HV
footprint 0603S
pins: 1, 2

## RC0603FR-07390KL
designator R?  ValueDisplayed: 390k  (hidden comment: RC0603FR-07390KL)
RES, 390 k, 1%, 0.1 W, 0603; Manufacturer: Yageo America; CompType: Resistor; Value: 390k; Res_ohm: 390000; Tolerance_%: 1; Power_W: 0.1; Value2: 0.1W; VDC_V: 150; TempCo: 200 ppm/C; SizeArea_mm2: 1.28; SizeX_mm: 1.6; SizeY_mm: 0.8; U/M: EA; AEC Category: Q200
signal-integrity model Resistor
simulation model Resistor
footprint 0603
footprint 0603M
footprint 0603L
footprint 0603_HV
footprint 0603S
pins: 1, 2

## RC0603FR-07390RL
designator R?  ValueDisplayed: 390  (hidden comment: RC0603FR-07390RL)
RES, 390, 1%, 0.1 W, 0603; Manufacturer: Yageo America; CompType: Resistor; Value: 390; Value_Code: 390R; Tolerance_%: 1; Power_W: 0.1; Value2: 0.1W; VDC_V: 150; TempCo: 200 ppm/C; SizeArea_mm2: 1.28; SizeX_mm: 1.6; SizeY_mm: 0.8; U/M: EA; AEC Category: Q200; Green_Lifecycle: Active; Green_REACh: Passed
signal-integrity model Resistor
simulation model Resistor
footprint 0603
footprint 0603M
footprint 0603L
footprint 0603_HV
footprint 0603S
pins: 1, 2

## RC0603FR-07392KL
designator R?  ValueDisplayed: 392k  (hidden comment: RC0603FR-07392KL)
RES, 392 k, 1%, 0.1 W, 0603; Manufacturer: Yageo America; CompType: Resistor; Value: 392k; Res_ohm: 392000; Tolerance_%: 1; Power_W: 0.1; Value2: 0.1W; VDC_V: 150; TempCo: 200 ppm/C; SizeArea_mm2: 1.28; SizeX_mm: 1.6; SizeY_mm: 0.8; EIA_Code: E96; U/M: EA; AEC Category: Q200; Green_Lifecycle: Active; Green_REACh: Passed
signal-integrity model Resistor
simulation model Resistor
footprint 0603
footprint 0603M
footprint 0603L
footprint 0603_HV
footprint 0603S
pins: 1, 2

## RC0603FR-07392RL
designator R?  ValueDisplayed: 392  (hidden comment: RC0603FR-07392RL)
RES, 392, 1%, 0.1 W, 0603; Manufacturer: Yageo America; CompType: Resistor; Value: 392; Value_Code: 392R; Tolerance_%: 1; Power_W: 0.1; Value2: 0.1W; VDC_V: 150; TempCo: 200 ppm/C; SizeArea_mm2: 1.28; SizeX_mm: 1.6; SizeY_mm: 0.8; EIA_Code: E96; U/M: EA; AEC Category: Q200
signal-integrity model Resistor
simulation model Resistor
footprint 0603
footprint 0603M
footprint 0603L
footprint 0603_HV
footprint 0603S
pins: 1, 2

## RC0603FR-07402KL
designator R?  ValueDisplayed: 402k  (hidden comment: RC0603FR-07402KL)
RES, 402 k, 1%, 0.1 W, 0603; Manufacturer: Yageo America; CompType: Resistor; Value: 402k; Res_ohm: 402000; Tolerance_%: 1; Power_W: 0.1; Value2: 0.1W; VDC_V: 150; TempCo: 200 ppm/C; SizeArea_mm2: 1.28; SizeX_mm: 1.6; SizeY_mm: 0.8; EIA_Code: E96; U/M: EA; AEC Category: Q200; Green_Lifecycle: Active; Green_REACh: Passed
signal-integrity model Resistor
simulation model Resistor
footprint 0603
footprint 0603M
footprint 0603L
footprint 0603_HV
footprint 0603S
pins: 1, 2

## RC0603FR-07402RL
designator R?  ValueDisplayed: 402  (hidden comment: RC0603FR-07402RL)
RES, 402, 1%, 0.1 W, 0603; Manufacturer: Yageo America; CompType: Resistor; Value: 402; Value_Code: 402R; Tolerance_%: 1; Power_W: 0.1; Value2: 0.1W; VDC_V: 150; TempCo: 200 ppm/C; SizeArea_mm2: 1.28; SizeX_mm: 1.6; SizeY_mm: 0.8; EIA_Code: E96; U/M: EA; AEC Category: Q200; Green_Lifecycle: Active; Green_REACh: Passed
signal-integrity model Resistor
simulation model Resistor
footprint 0603
footprint 0603M
footprint 0603L
footprint 0603_HV
footprint 0603S
pins: 1, 2

## RC0603FR-07412KL
designator R?  ValueDisplayed: 412k  (hidden comment: RC0603FR-07412KL)
RES, 412 k, 1%, 0.1 W, 0603; Manufacturer: Yageo America; CompType: Resistor; Value: 412k; Res_ohm: 412000; Tolerance_%: 1; Power_W: 0.1; Value2: 0.1W; VDC_V: 150; TempCo: 200 ppm/C; SizeArea_mm2: 1.28; SizeX_mm: 1.6; SizeY_mm: 0.8; EIA_Code: E96; U/M: EA; AEC Category: Q200
signal-integrity model Resistor
simulation model Resistor
footprint 0603
footprint 0603M
footprint 0603L
footprint 0603_HV
footprint 0603S
pins: 1, 2

## RC0603FR-07412RL
designator R?  ValueDisplayed: 412  (hidden comment: RC0603FR-07412RL)
RES, 412, 1%, 0.1 W, 0603; Manufacturer: Yageo America; CompType: Resistor; Value: 412; Value_Code: 412R; Tolerance_%: 1; Power_W: 0.1; Value2: 0.1W; VDC_V: 150; TempCo: 200 ppm/C; SizeArea_mm2: 1.28; SizeX_mm: 1.6; SizeY_mm: 0.8; EIA_Code: E96; U/M: EA; AEC Category: Q200; Green_Lifecycle: Active; Green_REACh: Passed
signal-integrity model Resistor
simulation model Resistor
footprint 0603
footprint 0603M
footprint 0603L
footprint 0603_HV
footprint 0603S
pins: 1, 2

## RC0603FR-07422KL
designator R?  ValueDisplayed: 422k  (hidden comment: RC0603FR-07422KL)
RES, 422 k, 1%, 0.1 W, 0603; Manufacturer: Yageo America; CompType: Resistor; Value: 422k; Res_ohm: 422000; Tolerance_%: 1; Power_W: 0.1; Value2: 0.1W; VDC_V: 150; TempCo: 200 ppm/C; SizeArea_mm2: 1.28; SizeX_mm: 1.6; SizeY_mm: 0.8; EIA_Code: E96; U/M: EA; AEC Category: Q200
signal-integrity model Resistor
simulation model Resistor
footprint 0603
footprint 0603M
footprint 0603L
footprint 0603_HV
footprint 0603S
pins: 1, 2

## RC0603FR-07422RL
designator R?  ValueDisplayed: 422  (hidden comment: RC0603FR-07422RL)
RES, 422, 1%, 0.1 W, 0603; Manufacturer: Yageo America; CompType: Resistor; Value: 422; Value_Code: 422R; Tolerance_%: 1; Power_W: 0.1; Value2: 0.1W; VDC_V: 150; TempCo: 200 ppm/C; SizeArea_mm2: 1.28; SizeX_mm: 1.6; SizeY_mm: 0.8; EIA_Code: E96; U/M: EA; AEC Category: Q200
signal-integrity model Resistor
simulation model Resistor
footprint 0603
footprint 0603M
footprint 0603L
footprint 0603_HV
footprint 0603S
pins: 1, 2

## RC0603FR-07430KL
designator R?  ValueDisplayed: 430k  (hidden comment: RC0603FR-07430KL)
RES, 430 k, 1%, 0.1 W, 0603; Manufacturer: Yageo America; CompType: Resistor; Value: 430k; Res_ohm: 430000; Tolerance_%: 1; Power_W: 0.1; Value2: 0.1W; VDC_V: 150; TempCo: 200 ppm/C; SizeArea_mm2: 1.28; SizeX_mm: 1.6; SizeY_mm: 0.8; U/M: EA; AEC Category: Q200; Green_Lifecycle: Active; Green_REACh: Passed
signal-integrity model Resistor
simulation model Resistor
footprint 0603
footprint 0603M
footprint 0603L
footprint 0603_HV
footprint 0603S
pins: 1, 2

## RC0603FR-07430RL
designator R?  ValueDisplayed: 430  (hidden comment: RC0603FR-07430RL)
RES, 430, 1%, 0.1 W, 0603; Manufacturer: Yageo America; CompType: Resistor; Value: 430; Value_Code: 430R; Tolerance_%: 1; Power_W: 0.1; Value2: 0.1W; VDC_V: 150; TempCo: 200 ppm/C; SizeArea_mm2: 1.28; SizeX_mm: 1.6; SizeY_mm: 0.8; U/M: EA; AEC Category: Q200; Green_Lifecycle: Active; Green_REACh: Passed
signal-integrity model Resistor
simulation model Resistor
footprint 0603
footprint 0603M
footprint 0603L
footprint 0603_HV
footprint 0603S
pins: 1, 2

## RC0603FR-07432KL
designator R?  ValueDisplayed: 432k  (hidden comment: RC0603FR-07432KL)
RES, 432 k, 1%, 0.1 W, 0603; Manufacturer: Yageo America; CompType: Resistor; Value: 432k; Res_ohm: 432000; Tolerance_%: 1; Power_W: 0.1; Value2: 0.1W; VDC_V: 150; TempCo: 200 ppm/C; SizeArea_mm2: 1.28; SizeX_mm: 1.6; SizeY_mm: 0.8; EIA_Code: E96; U/M: EA; AEC Category: Q200
signal-integrity model Resistor
simulation model Resistor
footprint 0603
footprint 0603M
footprint 0603L
footprint 0603_HV
footprint 0603S
pins: 1, 2

## RC0603FR-07432RL
designator R?  ValueDisplayed: 432  (hidden comment: RC0603FR-07432RL)
RES, 432, 1%, 0.1 W, 0603; Manufacturer: Yageo America; CompType: Resistor; Value: 432; Value_Code: 432R; Tolerance_%: 1; Power_W: 0.1; Value2: 0.1W; VDC_V: 150; TempCo: 200 ppm/C; SizeArea_mm2: 1.28; SizeX_mm: 1.6; SizeY_mm: 0.8; EIA_Code: E96; U/M: EA; AEC Category: Q200
signal-integrity model Resistor
simulation model Resistor
footprint 0603
footprint 0603M
footprint 0603L
footprint 0603_HV
footprint 0603S
pins: 1, 2

## RC0603FR-07442KL
designator R?  ValueDisplayed: 442k  (hidden comment: RC0603FR-07442KL)
RES, 442 k, 1%, 0.1 W, 0603; Manufacturer: Yageo America; CompType: Resistor; Value: 442k; Res_ohm: 442000; Tolerance_%: 1; Power_W: 0.1; Value2: 0.1W; VDC_V: 150; TempCo: 200 ppm/C; SizeArea_mm2: 1.28; SizeX_mm: 1.6; SizeY_mm: 0.8; EIA_Code: E96; U/M: EA; AEC Category: Q200; Green_Lifecycle: Active; Green_REACh: Passed
signal-integrity model Resistor
simulation model Resistor
footprint 0603
footprint 0603M
footprint 0603L
footprint 0603_HV
footprint 0603S
pins: 1, 2

## RC0603FR-07442RL
designator R?  ValueDisplayed: 442  (hidden comment: RC0603FR-07442RL)
RES, 442, 1%, 0.1 W, 0603; Manufacturer: Yageo America; CompType: Resistor; Value: 442; Value_Code: 442R; Tolerance_%: 1; Power_W: 0.1; Value2: 0.1W; VDC_V: 150; TempCo: 200 ppm/C; SizeArea_mm2: 1.28; SizeX_mm: 1.6; SizeY_mm: 0.8; EIA_Code: E96; U/M: EA; AEC Category: Q200
signal-integrity model Resistor
simulation model Resistor
footprint 0603
footprint 0603M
footprint 0603L
footprint 0603_HV
footprint 0603S
pins: 1, 2

## RC0603FR-07453KL
designator R?  ValueDisplayed: 453k  (hidden comment: RC0603FR-07453KL)
RES, 453 k, 1%, 0.1 W, 0603; Manufacturer: Yageo America; CompType: Resistor; Value: 453k; Res_ohm: 453000; Tolerance_%: 1; Power_W: 0.1; Value2: 0.1W; VDC_V: 150; TempCo: 200 ppm/C; SizeArea_mm2: 1.28; SizeX_mm: 1.6; SizeY_mm: 0.8; EIA_Code: E96; U/M: EA; AEC Category: Q200
signal-integrity model Resistor
simulation model Resistor
footprint 0603
footprint 0603M
footprint 0603L
footprint 0603_HV
footprint 0603S
pins: 1, 2

## RC0603FR-07453RL
designator R?  ValueDisplayed: 453  (hidden comment: RC0603FR-07453RL)
RES, 453, 1%, 0.1 W, 0603; Manufacturer: Yageo America; CompType: Resistor; Value: 453; Value_Code: 453R; Tolerance_%: 1; Power_W: 0.1; Value2: 0.1W; VDC_V: 150; TempCo: 200 ppm/C; SizeArea_mm2: 1.28; SizeX_mm: 1.6; SizeY_mm: 0.8; EIA_Code: E96; U/M: EA; AEC Category: Q200; Green_Lifecycle: Active; Green_REACh: Passed
signal-integrity model Resistor
simulation model Resistor
footprint 0603
footprint 0603M
footprint 0603L
footprint 0603_HV
footprint 0603S
pins: 1, 2

## RC0603FR-07464KL
designator R?  ValueDisplayed: 464k  (hidden comment: RC0603FR-07464KL)
RES, 464 k, 1%, 0.1 W, 0603; Manufacturer: Yageo America; CompType: Resistor; Value: 464k; Res_ohm: 464000; Tolerance_%: 1; Power_W: 0.1; Value2: 0.1W; VDC_V: 150; TempCo: 200 ppm/C; SizeArea_mm2: 1.28; SizeX_mm: 1.6; SizeY_mm: 0.8; EIA_Code: E96; U/M: EA; AEC Category: Q200
signal-integrity model Resistor
simulation model Resistor
footprint 0603
footprint 0603M
footprint 0603L
footprint 0603_HV
footprint 0603S
pins: 1, 2

## RC0603FR-07464RL
designator R?  ValueDisplayed: 464  (hidden comment: RC0603FR-07464RL)
RES, 464, 1%, 0.1 W, 0603; Manufacturer: Yageo America; CompType: Resistor; Value: 464; Value_Code: 464R; Tolerance_%: 1; Power_W: 0.1; Value2: 0.1W; VDC_V: 150; TempCo: 200 ppm/C; SizeArea_mm2: 1.28; SizeX_mm: 1.6; SizeY_mm: 0.8; EIA_Code: E96; U/M: EA; AEC Category: Q200
signal-integrity model Resistor
simulation model Resistor
footprint 0603
footprint 0603M
footprint 0603L
footprint 0603_HV
footprint 0603S
pins: 1, 2

## RC0603FR-07470KL
designator R?  ValueDisplayed: 470k  (hidden comment: RC0603FR-07470KL)
RES, 470 k, 1%, 0.1 W, 0603; Manufacturer: Yageo America; CompType: Resistor; Value: 470k; Res_ohm: 470000; Tolerance_%: 1; Power_W: 0.1; Value2: 0.1W; VDC_V: 150; TempCo: 200 ppm/C; SizeArea_mm2: 1.28; SizeX_mm: 1.6; SizeY_mm: 0.8; U/M: EA; AEC Category: Q200; Green_Lifecycle: Active; Green_REACh: Passed
signal-integrity model Resistor
simulation model Resistor
footprint 0603
footprint 0603M
footprint 0603L
footprint 0603_HV
footprint 0603S
pins: 1, 2

## RC0603FR-07470RL
designator R?  ValueDisplayed: 470  (hidden comment: RC0603FR-07470RL)
RES, 470, 1%, 0.1 W, 0603; Manufacturer: Yageo America; CompType: Resistor; Value: 470; Value_Code: 470R; Tolerance_%: 1; Power_W: 0.1; Value2: 0.1W; VDC_V: 150; TempCo: 200 ppm/C; SizeArea_mm2: 1.28; SizeX_mm: 1.6; SizeY_mm: 0.8; U/M: EA; AEC Category: Q200; Green_Lifecycle: Active; Green_REACh: Passed
signal-integrity model Resistor
simulation model Resistor
footprint 0603
footprint 0603M
footprint 0603L
footprint 0603_HV
footprint 0603S
pins: 1, 2

## RC0603FR-07475KL
designator R?  ValueDisplayed: 475k  (hidden comment: RC0603FR-07475KL)
RES, 475 k, 1%, 0.1 W, 0603; Manufacturer: Yageo America; CompType: Resistor; Value: 475k; Res_ohm: 475000; Tolerance_%: 1; Power_W: 0.1; Value2: 0.1W; VDC_V: 150; TempCo: 200 ppm/C; SizeArea_mm2: 1.28; SizeX_mm: 1.6; SizeY_mm: 0.8; EIA_Code: E96; U/M: EA; AEC Category: Q200; Green_Lifecycle: Active; Green_REACh: Passed
signal-integrity model Resistor
simulation model Resistor
footprint 0603
footprint 0603M
footprint 0603L
footprint 0603_HV
footprint 0603S
pins: 1, 2

## RC0603FR-07475RL
designator R?  ValueDisplayed: 475  (hidden comment: RC0603FR-07475RL)
RES, 475, 1%, 0.1 W, 0603; Manufacturer: Yageo America; CompType: Resistor; Value: 475; Value_Code: 475R; Tolerance_%: 1; Power_W: 0.1; Value2: 0.1W; VDC_V: 150; TempCo: 200 ppm/C; SizeArea_mm2: 1.28; SizeX_mm: 1.6; SizeY_mm: 0.8; EIA_Code: E96; U/M: EA; AEC Category: Q200; Green_Lifecycle: Active; Green_REACh: Passed
signal-integrity model Resistor
simulation model Resistor
footprint 0603
footprint 0603M
footprint 0603L
footprint 0603_HV
footprint 0603S
pins: 1, 2

## RC0603FR-07487KL
designator R?  ValueDisplayed: 487k  (hidden comment: RC0603FR-07487KL)
RES, 487 k, 1%, 0.1 W, 0603; Manufacturer: Yageo America; CompType: Resistor; Value: 487k; Res_ohm: 487000; Tolerance_%: 1; Power_W: 0.1; Value2: 0.1W; VDC_V: 150; TempCo: 200 ppm/C; SizeArea_mm2: 1.28; SizeX_mm: 1.6; SizeY_mm: 0.8; EIA_Code: E96; U/M: EA; AEC Category: Q200
signal-integrity model Resistor
simulation model Resistor
footprint 0603
footprint 0603M
footprint 0603L
footprint 0603_HV
footprint 0603S
pins: 1, 2

## RC0603FR-07487RL
designator R?  ValueDisplayed: 487  (hidden comment: RC0603FR-07487RL)
RES, 487, 1%, 0.1 W, 0603; Manufacturer: Yageo America; CompType: Resistor; Value: 487; Value_Code: 487R; Tolerance_%: 1; Power_W: 0.1; Value2: 0.1W; VDC_V: 150; TempCo: 200 ppm/C; SizeArea_mm2: 1.28; SizeX_mm: 1.6; SizeY_mm: 0.8; EIA_Code: E96; U/M: EA; AEC Category: Q200
signal-integrity model Resistor
simulation model Resistor
footprint 0603
footprint 0603M
footprint 0603L
footprint 0603_HV
footprint 0603S
pins: 1, 2

## RC0603FR-07499KL
designator R?  ValueDisplayed: 499k  (hidden comment: RC0603FR-07499KL)
RES, 499 k, 1%, 0.1 W, 0603; Manufacturer: Yageo America; CompType: Resistor; Value: 499k; Res_ohm: 499000; Tolerance_%: 1; Power_W: 0.1; Value2: 0.1W; VDC_V: 150; TempCo: 200 ppm/C; SizeArea_mm2: 1.28; SizeX_mm: 1.6; SizeY_mm: 0.8; EIA_Code: E96; U/M: EA; AEC Category: Q200; Green_Lifecycle: Active; Green_REACh: Passed
signal-integrity model Resistor
simulation model Resistor
footprint 0603
footprint 0603M
footprint 0603L
footprint 0603_HV
footprint 0603S
pins: 1, 2

## RC0603FR-07499RL
designator R?  ValueDisplayed: 499  (hidden comment: RC0603FR-07499RL)
RES, 499, 1%, 0.1 W, 0603; Manufacturer: Yageo America; CompType: Resistor; Value: 499; Value_Code: 499R; Tolerance_%: 1; Power_W: 0.1; Value2: 0.1W; VDC_V: 150; TempCo: 200 ppm/C; SizeArea_mm2: 1.28; SizeX_mm: 1.6; SizeY_mm: 0.8; EIA_Code: E96; U/M: EA; AEC Category: Q200; Green_Lifecycle: Active; Green_REACh: Passed
signal-integrity model Resistor
simulation model Resistor
footprint 0603
footprint 0603M
footprint 0603L
footprint 0603_HV
footprint 0603S
pins: 1, 2

## RC0603FR-07510KL
designator R?  ValueDisplayed: 510k  (hidden comment: RC0603FR-07510KL)
RES, 510 k, 1%, 0.1 W, 0603; Manufacturer: Yageo America; CompType: Resistor; Value: 510k; Res_ohm: 510000; Tolerance_%: 1; Power_W: 0.1; Value2: 0.1W; VDC_V: 150; TempCo: 200 ppm/C; SizeArea_mm2: 1.28; SizeX_mm: 1.6; SizeY_mm: 0.8; U/M: EA; AEC Category: Q200
signal-integrity model Resistor
simulation model Resistor
footprint 0603
footprint 0603M
footprint 0603L
footprint 0603_HV
footprint 0603S
pins: 1, 2

## RC0603FR-07510RL
designator R?  ValueDisplayed: 510  (hidden comment: RC0603FR-07510RL)
RES, 510, 1%, 0.1 W, 0603; Manufacturer: Yageo America; CompType: Resistor; Value: 510; Value_Code: 510R; Tolerance_%: 1; Power_W: 0.1; Value2: 0.1W; VDC_V: 150; TempCo: 200 ppm/C; SizeArea_mm2: 1.28; SizeX_mm: 1.6; SizeY_mm: 0.8; U/M: EA; AEC Category: Q200; Green_Lifecycle: Active; Green_REACh: Passed
signal-integrity model Resistor
simulation model Resistor
footprint 0603
footprint 0603M
footprint 0603L
footprint 0603_HV
footprint 0603S
pins: 1, 2

## RC0603FR-07511KL
designator R?  ValueDisplayed: 511k  (hidden comment: RC0603FR-07511KL)
RES, 511 k, 1%, 0.1 W, 0603; Manufacturer: Yageo America; CompType: Resistor; Value: 511k; Res_ohm: 511000; Tolerance_%: 1; Power_W: 0.1; Value2: 0.1W; VDC_V: 150; TempCo: 200 ppm/C; SizeArea_mm2: 1.28; SizeX_mm: 1.6; SizeY_mm: 0.8; EIA_Code: E96; U/M: EA; AEC Category: Q200; Green_Lifecycle: Active; Green_REACh: Passed
signal-integrity model Resistor
simulation model Resistor
footprint 0603
footprint 0603M
footprint 0603L
footprint 0603_HV
footprint 0603S
pins: 1, 2

## RC0603FR-07511RL
designator R?  ValueDisplayed: 511  (hidden comment: RC0603FR-07511RL)
RES, 511, 1%, 0.1 W, 0603; Manufacturer: Yageo America; CompType: Resistor; Value: 511; Value_Code: 511R; Tolerance_%: 1; Power_W: 0.1; Value2: 0.1W; VDC_V: 150; TempCo: 200 ppm/C; SizeArea_mm2: 1.28; SizeX_mm: 1.6; SizeY_mm: 0.8; EIA_Code: E96; U/M: EA; AEC Category: Q200
signal-integrity model Resistor
simulation model Resistor
footprint 0603
footprint 0603M
footprint 0603L
footprint 0603_HV
footprint 0603S
pins: 1, 2

## RC0603FR-07523KL
designator R?  ValueDisplayed: 523k  (hidden comment: RC0603FR-07523KL)
RES, 523 k, 1%, 0.1 W, 0603; Manufacturer: Yageo America; CompType: Resistor; Value: 523k; Res_ohm: 523000; Tolerance_%: 1; Power_W: 0.1; Value2: 0.1W; VDC_V: 150; TempCo: 200 ppm/C; SizeArea_mm2: 1.28; SizeX_mm: 1.6; SizeY_mm: 0.8; EIA_Code: E96; U/M: EA; AEC Category: Q200; Green_Lifecycle: Active; Green_REACh: Passed
signal-integrity model Resistor
simulation model Resistor
footprint 0603
footprint 0603M
footprint 0603L
footprint 0603_HV
footprint 0603S
pins: 1, 2

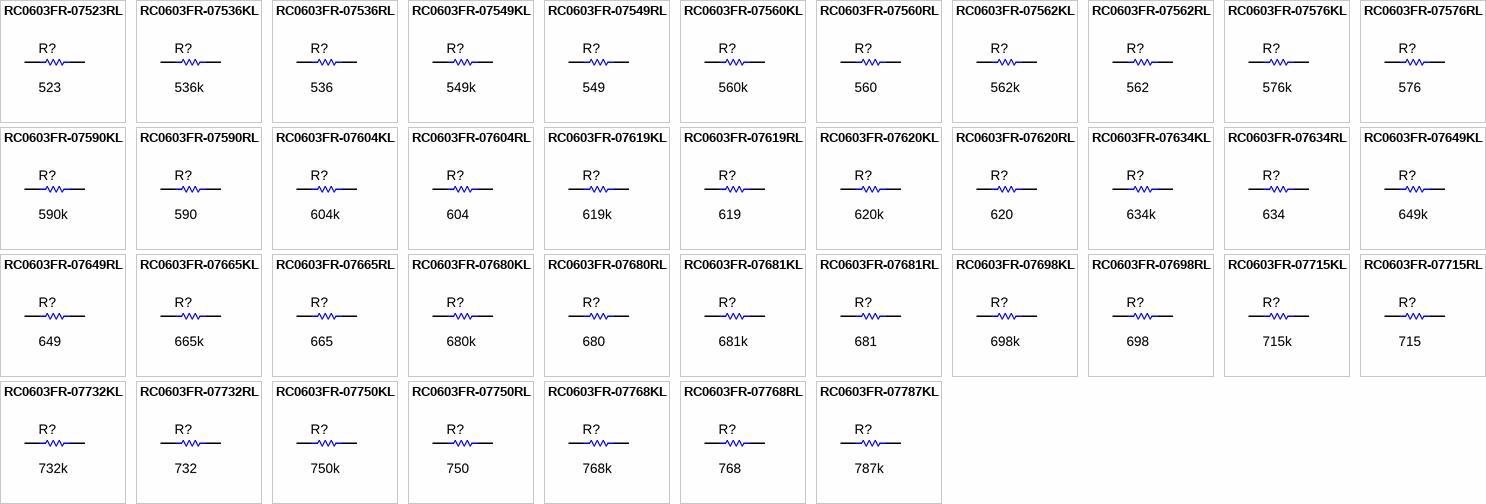
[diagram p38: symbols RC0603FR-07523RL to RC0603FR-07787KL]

## RC0603FR-07523RL
designator R?  ValueDisplayed: 523  (hidden comment: RC0603FR-07523RL)
RES, 523, 1%, 0.1 W, 0603; Manufacturer: Yageo America; CompType: Resistor; Value: 523; Value_Code: 523R; Tolerance_%: 1; Power_W: 0.1; Value2: 0.1W; VDC_V: 150; TempCo: 200 ppm/C; SizeArea_mm2: 1.28; SizeX_mm: 1.6; SizeY_mm: 0.8; EIA_Code: E96; U/M: EA; AEC Category: Q200
signal-integrity model Resistor
simulation model Resistor
footprint 0603
footprint 0603M
footprint 0603L
footprint 0603_HV
footprint 0603S
pins: 1, 2

## RC0603FR-07536KL
designator R?  ValueDisplayed: 536k  (hidden comment: RC0603FR-07536KL)
RES, 536 k, 1%, 0.1 W, 0603; Manufacturer: Yageo America; CompType: Resistor; Value: 536k; Res_ohm: 536000; Tolerance_%: 1; Power_W: 0.1; Value2: 0.1W; VDC_V: 150; TempCo: 200 ppm/C; SizeArea_mm2: 1.28; SizeX_mm: 1.6; SizeY_mm: 0.8; EIA_Code: E96; U/M: EA; AEC Category: Q200
signal-integrity model Resistor
simulation model Resistor
footprint 0603
footprint 0603M
footprint 0603L
footprint 0603_HV
footprint 0603S
pins: 1, 2

## RC0603FR-07536RL
designator R?  ValueDisplayed: 536  (hidden comment: RC0603FR-07536RL)
RES, 536, 1%, 0.1 W, 0603; Manufacturer: Yageo America; CompType: Resistor; Value: 536; Value_Code: 536R; Tolerance_%: 1; Power_W: 0.1; Value2: 0.1W; VDC_V: 150; TempCo: 200 ppm/C; SizeArea_mm2: 1.28; SizeX_mm: 1.6; SizeY_mm: 0.8; EIA_Code: E96; U/M: EA; AEC Category: Q200
signal-integrity model Resistor
simulation model Resistor
footprint 0603
footprint 0603M
footprint 0603L
footprint 0603_HV
footprint 0603S
pins: 1, 2

## RC0603FR-07549KL
designator R?  ValueDisplayed: 549k  (hidden comment: RC0603FR-07549KL)
RES, 549 k, 1%, 0.1 W, 0603; Manufacturer: Yageo America; CompType: Resistor; Value: 549k; Res_ohm: 549000; Tolerance_%: 1; Power_W: 0.1; Value2: 0.1W; VDC_V: 150; TempCo: 200 ppm/C; SizeArea_mm2: 1.28; SizeX_mm: 1.6; SizeY_mm: 0.8; EIA_Code: E96; U/M: EA; AEC Category: Q200; Green_Lifecycle: Active; Green_REACh: Passed
signal-integrity model Resistor
simulation model Resistor
footprint 0603
footprint 0603M
footprint 0603L
footprint 0603_HV
footprint 0603S
pins: 1, 2

## RC0603FR-07549RL
designator R?  ValueDisplayed: 549  (hidden comment: RC0603FR-07549RL)
RES, 549, 1%, 0.1 W, 0603; Manufacturer: Yageo America; CompType: Resistor; Value: 549; Value_Code: 549R; Tolerance_%: 1; Power_W: 0.1; Value2: 0.1W; VDC_V: 150; TempCo: 200 ppm/C; SizeArea_mm2: 1.28; SizeX_mm: 1.6; SizeY_mm: 0.8; EIA_Code: E96; U/M: EA; AEC Category: Q200; Green_Lifecycle: Active; Green_REACh: Passed
signal-integrity model Resistor
simulation model Resistor
footprint 0603
footprint 0603M
footprint 0603L
footprint 0603_HV
footprint 0603S
pins: 1, 2

## RC0603FR-07560KL
designator R?  ValueDisplayed: 560k  (hidden comment: RC0603FR-07560KL)
RES, 560 k, 1%, 0.1 W, 0603; Manufacturer: Yageo America; CompType: Resistor; Value: 560k; Res_ohm: 560000; Tolerance_%: 1; Power_W: 0.1; Value2: 0.1W; VDC_V: 150; TempCo: 200 ppm/C; SizeArea_mm2: 1.28; SizeX_mm: 1.6; SizeY_mm: 0.8; U/M: EA; AEC Category: Q200; Green_Lifecycle: Active; Green_REACh: Passed
signal-integrity model Resistor
simulation model Resistor
footprint 0603
footprint 0603M
footprint 0603L
footprint 0603_HV
footprint 0603S
pins: 1, 2

## RC0603FR-07560RL
designator R?  ValueDisplayed: 560  (hidden comment: RC0603FR-07560RL)
RES, 560, 1%, 0.1 W, 0603; Manufacturer: Yageo America; CompType: Resistor; Value: 560; Value_Code: 560R; Tolerance_%: 1; Power_W: 0.1; Value2: 0.1W; VDC_V: 150; TempCo: 200 ppm/C; SizeArea_mm2: 1.28; SizeX_mm: 1.6; SizeY_mm: 0.8; U/M: EA; AEC Category: Q200; Green_Lifecycle: Active; Green_REACh: Passed
signal-integrity model Resistor
simulation model Resistor
footprint 0603
footprint 0603M
footprint 0603L
footprint 0603_HV
footprint 0603S
pins: 1, 2

## RC0603FR-07562KL
designator R?  ValueDisplayed: 562k  (hidden comment: RC0603FR-07562KL)
RES, 562 k, 1%, 0.1 W, 0603; Manufacturer: Yageo America; CompType: Resistor; Value: 562k; Res_ohm: 562000; Tolerance_%: 1; Power_W: 0.1; Value2: 0.1W; VDC_V: 150; TempCo: 200 ppm/C; SizeArea_mm2: 1.28; SizeX_mm: 1.6; SizeY_mm: 0.8; EIA_Code: E96; U/M: EA; AEC Category: Q200; Green_Lifecycle: Active; Green_REACh: Passed
signal-integrity model Resistor
simulation model Resistor
footprint 0603
footprint 0603M
footprint 0603L
footprint 0603_HV
footprint 0603S
pins: 1, 2

## RC0603FR-07562RL
designator R?  ValueDisplayed: 562  (hidden comment: RC0603FR-07562RL)
RES, 562, 1%, 0.1 W, 0603; Manufacturer: Yageo America; CompType: Resistor; Value: 562; Value_Code: 562R; Tolerance_%: 1; Power_W: 0.1; Value2: 0.1W; VDC_V: 150; TempCo: 200 ppm/C; SizeArea_mm2: 1.28; SizeX_mm: 1.6; SizeY_mm: 0.8; EIA_Code: E96; U/M: EA; AEC Category: Q200
signal-integrity model Resistor
simulation model Resistor
footprint 0603
footprint 0603M
footprint 0603L
footprint 0603_HV
footprint 0603S
pins: 1, 2

## RC0603FR-07576KL
designator R?  ValueDisplayed: 576k  (hidden comment: RC0603FR-07576KL)
RES, 576 k, 1%, 0.1 W, 0603; Manufacturer: Yageo America; CompType: Resistor; Value: 576k; Res_ohm: 576000; Tolerance_%: 1; Power_W: 0.1; Value2: 0.1W; VDC_V: 150; TempCo: 200 ppm/C; SizeArea_mm2: 1.28; SizeX_mm: 1.6; SizeY_mm: 0.8; EIA_Code: E96; U/M: EA; AEC Category: Q200
signal-integrity model Resistor
simulation model Resistor
footprint 0603
footprint 0603M
footprint 0603L
footprint 0603_HV
footprint 0603S
pins: 1, 2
